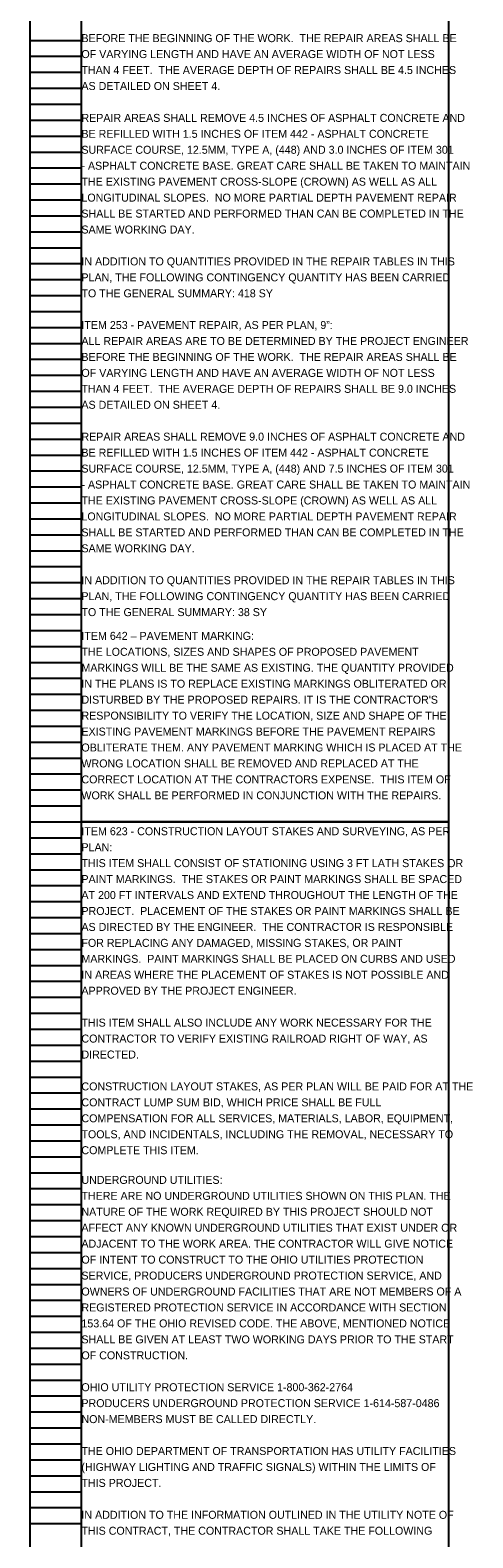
# Model space of a CAD drawing. Extents: x 16456 to 16500, y 5400 to 5823.
# Drawn here: x 16463.05 to 16470.82, y 5770.58 to 5797.05 of the extents above; entities that cross this region are included whole.
import ezdxf

# ---------------------------------------------------------------- set-up
doc = ezdxf.new("R2010")
doc.units = 0
for name, color, linetype in [('Default', 7, 'Continuous'), ('SC_Scratch1', 7, 'Continuous'), ('SH_Data', 7, 'Continuous')]:
    doc.layers.add(name, color=color, linetype=linetype)

msp = doc.modelspace()

# ---------------------------------------------------------------- linework, layer by layer
at = {"layer": 'SC_Scratch1'}
for points in [[(16463.949, 5803.312), (16470.389, 5803.312), (16470.389, 5783.152), (16463.949, 5783.152)], [(16463.949, 5783.152), (16470.389, 5783.152), (16470.389, 5762.992), (16463.949, 5762.992)]]:
    msp.add_lwpolyline(points, close=True, dxfattribs=at)
at = {"layer": 'SH_Data'}
for p, q in [((16463.049, 5783.152), (16463.049, 5803.312)), ((16463.949, 5783.152), (16463.949, 5803.312)), ((16463.049, 5796.872), (16463.949, 5796.872)), ((16463.049, 5796.592), (16463.949, 5796.592)), ((16463.049, 5796.312), (16463.949, 5796.312)), ((16463.049, 5796.032), (16463.949, 5796.032)), ((16463.049, 5795.752), (16463.949, 5795.752)), ((16463.049, 5795.472), (16463.949, 5795.472)), ((16463.049, 5795.192), (16463.949, 5795.192)), ((16463.049, 5794.912), (16463.949, 5794.912)), ((16463.049, 5794.632), (16463.949, 5794.632)), ((16463.049, 5794.352), (16463.949, 5794.352)), ((16463.049, 5794.072), (16463.949, 5794.072)), ((16463.049, 5793.792), (16463.949, 5793.792)), ((16463.049, 5793.512), (16463.949, 5793.512)), ((16463.049, 5793.232), (16463.949, 5793.232)), ((16463.049, 5792.952), (16463.949, 5792.952)), ((16463.049, 5792.672), (16463.949, 5792.672)), ((16463.049, 5792.392), (16463.949, 5792.392)), ((16463.049, 5792.112), (16463.949, 5792.112)), ((16463.049, 5791.832), (16463.949, 5791.832)), ((16463.049, 5791.552), (16463.949, 5791.552)), ((16463.049, 5791.272), (16463.949, 5791.272)), ((16463.049, 5790.992), (16463.949, 5790.992)), ((16463.049, 5790.712), (16463.949, 5790.712)), ((16463.049, 5790.432), (16463.949, 5790.432)), ((16463.049, 5790.152), (16463.949, 5790.152)), ((16463.049, 5789.872), (16463.949, 5789.872)), ((16463.049, 5789.592), (16463.949, 5789.592)), ((16463.049, 5789.312), (16463.949, 5789.312)), ((16463.049, 5789.032), (16463.949, 5789.032)), ((16463.049, 5788.752), (16463.949, 5788.752)), ((16463.049, 5788.472), (16463.949, 5788.472)), ((16463.049, 5788.192), (16463.949, 5788.192)), ((16463.049, 5787.912), (16463.949, 5787.912)), ((16463.049, 5787.632), (16463.949, 5787.632)), ((16463.049, 5787.352), (16463.949, 5787.352)), ((16463.049, 5787.072), (16463.949, 5787.072)), ((16463.049, 5786.792), (16463.949, 5786.792)), ((16463.049, 5786.512), (16463.949, 5786.512)), ((16463.049, 5786.232), (16463.949, 5786.232)), ((16463.049, 5785.952), (16463.949, 5785.952)), ((16463.049, 5785.672), (16463.949, 5785.672)), ((16463.049, 5785.392), (16463.949, 5785.392)), ((16463.049, 5785.112), (16463.949, 5785.112)), ((16463.049, 5784.832), (16463.949, 5784.832)), ((16463.049, 5784.552), (16463.949, 5784.552)), ((16463.049, 5784.272), (16463.949, 5784.272)), ((16463.049, 5783.992), (16463.949, 5783.992)), ((16463.049, 5783.712), (16463.949, 5783.712)), ((16463.049, 5783.432), (16463.949, 5783.432)), ((16463.049, 5762.992), (16463.049, 5783.152)), ((16463.049, 5783.152), (16463.949, 5783.152)), ((16463.049, 5783.152), (16463.949, 5783.152)), ((16463.949, 5762.992), (16463.949, 5783.152)), ((16463.049, 5782.872), (16463.949, 5782.872)), ((16463.049, 5782.592), (16463.949, 5782.592)), ((16463.049, 5782.312), (16463.949, 5782.312)), ((16463.049, 5782.032), (16463.949, 5782.032)), ((16463.049, 5781.752), (16463.949, 5781.752)), ((16463.049, 5781.472), (16463.949, 5781.472)), ((16463.049, 5781.192), (16463.949, 5781.192)), ((16463.049, 5780.912), (16463.949, 5780.912)), ((16463.049, 5780.632), (16463.949, 5780.632)), ((16463.049, 5780.352), (16463.949, 5780.352)), ((16463.049, 5780.072), (16463.949, 5780.072)), ((16463.049, 5779.792), (16463.949, 5779.792)), ((16463.049, 5779.512), (16463.949, 5779.512)), ((16463.049, 5779.232), (16463.949, 5779.232)), ((16463.049, 5778.952), (16463.949, 5778.952)), ((16463.049, 5778.672), (16463.949, 5778.672)), ((16463.049, 5778.392), (16463.949, 5778.392)), ((16463.049, 5778.112), (16463.949, 5778.112)), ((16463.049, 5777.832), (16463.949, 5777.832)), ((16463.049, 5777.552), (16463.949, 5777.552)), ((16463.049, 5777.272), (16463.949, 5777.272)), ((16463.049, 5776.992), (16463.949, 5776.992)), ((16463.049, 5776.712), (16463.949, 5776.712)), ((16463.049, 5776.432), (16463.949, 5776.432)), ((16463.049, 5776.152), (16463.949, 5776.152)), ((16463.049, 5775.872), (16463.949, 5775.872)), ((16463.049, 5775.592), (16463.949, 5775.592)), ((16463.049, 5775.312), (16463.949, 5775.312)), ((16463.049, 5775.032), (16463.949, 5775.032)), ((16463.049, 5774.752), (16463.949, 5774.752)), ((16463.049, 5774.472), (16463.949, 5774.472)), ((16463.049, 5774.192), (16463.949, 5774.192)), ((16463.049, 5773.912), (16463.949, 5773.912)), ((16463.049, 5773.632), (16463.949, 5773.632)), ((16463.049, 5773.352), (16463.949, 5773.352)), ((16463.049, 5773.072), (16463.949, 5773.072)), ((16463.049, 5772.792), (16463.949, 5772.792)), ((16463.049, 5772.512), (16463.949, 5772.512)), ((16463.049, 5772.232), (16463.949, 5772.232)), ((16463.049, 5771.952), (16463.949, 5771.952)), ((16463.049, 5771.672), (16463.949, 5771.672)), ((16463.049, 5771.392), (16463.949, 5771.392)), ((16463.049, 5771.112), (16463.949, 5771.112)), ((16463.049, 5770.832), (16463.949, 5770.832))]:
    msp.add_line(p, q, dxfattribs=at)

# ---------------------------------------------------------------- texts
at = {"layer": 'Default'}
for s, p in [('BEFORE THE BEGINNING OF THE WORK.  THE REPAIR AREAS SHALL BE ', (16463.949, 5796.841)), ('OF VARYING LENGTH AND HAVE AN AVERAGE WIDTH OF NOT LESS ', (16463.949, 5796.561)), ('THAN 4 FEET.  THE AVERAGE DEPTH OF REPAIRS SHALL BE 4.5 INCHES ', (16463.949, 5796.281)), ('AS DETAILED ON SHEET 4.  ', (16463.949, 5796.001)), ('REPAIR AREAS SHALL REMOVE 4.5 INCHES OF ASPHALT CONCRETE AND ', (16463.949, 5795.441)), ('BE REFILLED WITH 1.5 INCHES OF ITEM 442 - ASPHALT CONCRETE ', (16463.949, 5795.161)), ('SURFACE COURSE, 12.5MM, TYPE A, (448) AND 3.0 INCHES OF ITEM 301 ', (16463.949, 5794.881)), ('- ASPHALT CONCRETE BASE. GREAT CARE SHALL BE TAKEN TO MAINTAIN ', (16463.949, 5794.601)), ('THE EXISTING PAVEMENT CROSS-SLOPE (CROWN) AS WELL AS ALL ', (16463.949, 5794.321)), ('LONGITUDINAL SLOPES.  NO MORE PARTIAL DEPTH PAVEMENT REPAIR ', (16463.949, 5794.041)), ('SHALL BE STARTED AND PERFORMED THAN CAN BE COMPLETED IN THE ', (16463.949, 5793.761)), ('SAME WORKING DAY.', (16463.949, 5793.481)), ('IN ADDITION TO QUANTITIES PROVIDED IN THE REPAIR TABLES IN THIS ', (16463.949, 5792.921)), ('PLAN, THE FOLLOWING CONTINGENCY QUANTITY HAS BEEN CARRIED ', (16463.949, 5792.641)), ('TO THE GENERAL SUMMARY: 418 SY', (16463.949, 5792.361)), ('ITEM 253 - PAVEMENT REPAIR, AS PER PLAN, 9”:', (16463.949, 5791.804)), ('ALL REPAIR AREAS ARE TO BE DETERMINED BY THE PROJECT ENGINEER ', (16463.949, 5791.524)), ('BEFORE THE BEGINNING OF THE WORK.  THE REPAIR AREAS SHALL BE ', (16463.949, 5791.244)), ('OF VARYING LENGTH AND HAVE AN AVERAGE WIDTH OF NOT LESS ', (16463.949, 5790.964)), ('THAN 4 FEET.  THE AVERAGE DEPTH OF REPAIRS SHALL BE 9.0 INCHES ', (16463.949, 5790.684)), ('AS DETAILED ON SHEET 4.  ', (16463.949, 5790.404)), ('REPAIR AREAS SHALL REMOVE 9.0 INCHES OF ASPHALT CONCRETE AND ', (16463.949, 5789.844)), ('BE REFILLED WITH 1.5 INCHES OF ITEM 442 - ASPHALT CONCRETE ', (16463.949, 5789.564)), ('SURFACE COURSE, 12.5MM, TYPE A, (448) AND 7.5 INCHES OF ITEM 301 ', (16463.949, 5789.284)), ('- ASPHALT CONCRETE BASE. GREAT CARE SHALL BE TAKEN TO MAINTAIN ', (16463.949, 5789.004)), ('THE EXISTING PAVEMENT CROSS-SLOPE (CROWN) AS WELL AS ALL ', (16463.949, 5788.724)), ('LONGITUDINAL SLOPES.  NO MORE PARTIAL DEPTH PAVEMENT REPAIR ', (16463.949, 5788.444)), ('SHALL BE STARTED AND PERFORMED THAN CAN BE COMPLETED IN THE ', (16463.949, 5788.164)), ('SAME WORKING DAY.', (16463.949, 5787.884)), ('IN ADDITION TO QUANTITIES PROVIDED IN THE REPAIR TABLES IN THIS ', (16463.949, 5787.324)), ('PLAN, THE FOLLOWING CONTINGENCY QUANTITY HAS BEEN CARRIED ', (16463.949, 5787.044)), ('TO THE GENERAL SUMMARY: 38 SY', (16463.949, 5786.764)), ('ITEM 642 – PAVEMENT MARKING:', (16463.949, 5786.347)), ('THE LOCATIONS, SIZES AND SHAPES OF PROPOSED PAVEMENT ', (16463.949, 5786.067)), ('MARKINGS WILL BE THE SAME AS EXISTING. THE QUANTITY PROVIDED ', (16463.949, 5785.787)), ('IN THE PLANS IS TO REPLACE EXISTING MARKINGS OBLITERATED OR ', (16463.949, 5785.507)), ("DISTURBED BY THE PROPOSED REPAIRS. IT IS THE CONTRACTOR'S ", (16463.949, 5785.227)), ('RESPONSIBILITY TO VERIFY THE LOCATION, SIZE AND SHAPE OF THE ', (16463.949, 5784.947)), ('EXISTING PAVEMENT MARKINGS BEFORE THE PAVEMENT REPAIRS ', (16463.949, 5784.667)), ('OBLITERATE THEM. ANY PAVEMENT MARKING WHICH IS PLACED AT THE ', (16463.949, 5784.387)), ('WRONG LOCATION SHALL BE REMOVED AND REPLACED AT THE ', (16463.949, 5784.107)), ('CORRECT LOCATION AT THE CONTRACTORS EXPENSE.  THIS ITEM OF ', (16463.949, 5783.827)), ('WORK SHALL BE PERFORMED IN CONJUNCTION WITH THE REPAIRS.', (16463.949, 5783.547)), ('ITEM 623 - CONSTRUCTION LAYOUT STAKES AND SURVEYING, AS PER ', (16463.949, 5782.917)), ('PLAN:', (16463.949, 5782.637)), ('THIS ITEM SHALL CONSIST OF STATIONING USING 3 FT LATH STAKES OR ', (16463.949, 5782.357)), ('PAINT MARKINGS.  THE STAKES OR PAINT MARKINGS SHALL BE SPACED ', (16463.949, 5782.077)), ('AT 200 FT INTERVALS AND EXTEND THROUGHOUT THE LENGTH OF THE ', (16463.949, 5781.797)), ('PROJECT.  PLACEMENT OF THE STAKES OR PAINT MARKINGS SHALL BE ', (16463.949, 5781.517)), ('AS DIRECTED BY THE ENGINEER.  THE CONTRACTOR IS RESPONSIBLE ', (16463.949, 5781.237)), ('FOR REPLACING ANY DAMAGED, MISSING STAKES, OR PAINT ', (16463.949, 5780.957)), ('MARKINGS.  PAINT MARKINGS SHALL BE PLACED ON CURBS AND USED ', (16463.949, 5780.677)), ('IN AREAS WHERE THE PLACEMENT OF STAKES IS NOT POSSIBLE AND ', (16463.949, 5780.397)), ('APPROVED BY THE PROJECT ENGINEER.', (16463.949, 5780.117)), ('THIS ITEM SHALL ALSO INCLUDE ANY WORK NECESSARY FOR THE ', (16463.949, 5779.557)), ('CONTRACTOR TO VERIFY EXISTING RAILROAD RIGHT OF WAY, AS ', (16463.949, 5779.277)), ('DIRECTED.', (16463.949, 5778.997)), ('CONSTRUCTION LAYOUT STAKES, AS PER PLAN WILL BE PAID FOR AT THE ', (16463.949, 5778.437)), ('CONTRACT LUMP SUM BID, WHICH PRICE SHALL BE FULL ', (16463.949, 5778.157)), ('COMPENSATION FOR ALL SERVICES, MATERIALS, LABOR, EQUIPMENT, ', (16463.949, 5777.877)), ('TOOLS, AND INCIDENTALS, INCLUDING THE REMOVAL, NECESSARY TO ', (16463.949, 5777.597)), ('COMPLETE THIS ITEM.', (16463.949, 5777.317)), ('UNDERGROUND UTILITIES:', (16463.949, 5776.796)), ('THERE ARE NO UNDERGROUND UTILITIES SHOWN ON THIS PLAN. THE ', (16463.949, 5776.516)), ('NATURE OF THE WORK REQUIRED BY THIS PROJECT SHOULD NOT ', (16463.949, 5776.236)), ('AFFECT ANY KNOWN UNDERGROUND UTILITIES THAT EXIST UNDER OR ', (16463.949, 5775.956)), ('ADJACENT TO THE WORK AREA. THE CONTRACTOR WILL GIVE NOTICE ', (16463.949, 5775.676)), ('OF INTENT TO CONSTRUCT TO THE OHIO UTILITIES PROTECTION ', (16463.949, 5775.396)), ('SERVICE, PRODUCERS UNDERGROUND PROTECTION SERVICE, AND ', (16463.949, 5775.116)), ('OWNERS OF UNDERGROUND FACILITIES THAT ARE NOT MEMBERS OF A ', (16463.949, 5774.836)), ('REGISTERED PROTECTION SERVICE IN ACCORDANCE WITH SECTION ', (16463.949, 5774.556)), ('153.64 OF THE OHIO REVISED CODE. THE ABOVE, MENTIONED NOTICE ', (16463.949, 5774.276)), ('SHALL BE GIVEN AT LEAST TWO WORKING DAYS PRIOR TO THE START ', (16463.949, 5773.996)), ('OF CONSTRUCTION.', (16463.949, 5773.716)), ('OHIO UTILITY PROTECTION SERVICE 1-800-362-2764', (16463.949, 5773.156)), ('PRODUCERS UNDERGROUND PROTECTION SERVICE 1-614-587-0486', (16463.949, 5772.876)), ('NON-MEMBERS MUST BE CALLED DIRECTLY.', (16463.949, 5772.596)), ('THE OHIO DEPARTMENT OF TRANSPORTATION HAS UTILITY FACILITIES ', (16463.949, 5772.036)), ('(HIGHWAY LIGHTING AND TRAFFIC SIGNALS) WITHIN THE LIMITS OF ', (16463.949, 5771.756)), ('THIS PROJECT.', (16463.949, 5771.476)), ('IN ADDITION TO THE INFORMATION OUTLINED IN THE UTILITY NOTE OF ', (16463.949, 5770.916)), ('THIS CONTRACT, THE CONTRACTOR SHALL TAKE THE FOLLOWING ', (16463.949, 5770.636))]:
    msp.add_text(s, height=0.14, dxfattribs=at).set_placement(p)

doc.saveas('drawing.dxf')
